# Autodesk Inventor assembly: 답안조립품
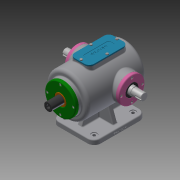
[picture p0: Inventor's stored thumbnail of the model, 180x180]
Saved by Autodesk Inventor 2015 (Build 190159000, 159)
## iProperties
Created: 2021-11
Part Number: 답안조립품
Document SubType Name: Assembly
Designer: G01
Author: G01
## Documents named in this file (14)
- C:\Users\G01\Desktop\711106V1010\답안조립품.iam
- C:\Users\G01\Desktop\711106V1010\베어링 6205.ipt
- 베어링 6205.ipt
- C:\Users\G01\Desktop\711106V1010\본체.ipt
- C:\Users\G01\Desktop\711106V1010\볼트 M4x0.7.ipt
- C:\Users\G01\Desktop\711106V1010\부시.ipt
- C:\Users\G01\Desktop\711106V1010\상부커버.ipt
- C:\Users\G01\Desktop\711106V1010\슬라이드 커버.ipt
- C:\Users\G01\Desktop\711106V1010\슬라이드.ipt
- C:\Users\G01\Desktop\711106V1010\오일실.ipt
- 오일실.ipt
- C:\Users\G01\Desktop\711106V1010\육각머리볼트 M4.ipt
- C:\Users\G01\Desktop\711106V1010\축 커버.ipt
- C:\Users\G01\Desktop\711106V1010\편심축.ipt
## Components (12 placed, 1 different names)
1. M4x0.7:1
2. M4x0.7:2
3. M4x0.7:3
4. M4x0.7:4
5. M4x0.7:5
6. M4x0.7:6
7. M4x0.7:7
8. M4x0.7:8
9. M4x0.7:9
10. M4x0.7:10
11. M4x0.7:11
12. M4x0.7:12
